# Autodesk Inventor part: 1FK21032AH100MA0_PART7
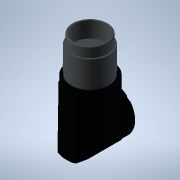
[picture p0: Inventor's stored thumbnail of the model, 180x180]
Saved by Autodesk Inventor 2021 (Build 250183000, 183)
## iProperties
Created: 2025-04
Part Number: 1FK21032AH100MA0_PART7
Material: Generic
Catalog Web Link: www.3dfindit.com
Description: -Servo synchronous motor
Document SubType Name: Modeling
Designer: psAdmin
Mass: 11.1504 g
Surface Area: 35.8996 cm^2
Volume: 11.1504 cm^3
Density: 1 g/cm^3
Appearance: PSOLRGB-176-176-176
Category: PARTsolutions
Title: 1FK21032AH100MA0_PART7
Author: Cadenas PARTsolutions
Comments: Servo synchronous motor
Sending System: PARTsolutions
Preprocessor: ST-DEVELOPER v19.3
PSOL_IDENT_0: {$CADENAS_DATA/23d-libs/siemens_ag/_cat_/12/33/1fk21032ah100ma0.prj},213 {VTYP=3D},{NB=1FK21032AH100
PSOL_IDENT_1: MA0_PART7},{LINA=1FK21032AH100MA0_PART7},{NN=1FK21032AH100MA0_PART7},{NOPRJ=TRUE},{DATE=19.08.2025 1
PSOL_IDENT_2: 4:00:27},{GEOMDATE=30.07.2025 02:02:58},{VERSION=},{LINEID=10},{WBVAR=},{WBNUMERIC=}  {NB=1FK21032AH
PSOL_IDENT_3: 100MA0_PART7},{LINA=1FK21032AH100MA0_PART7},{KT=DUMMY},{PREVIEW=../../../_pool_/d3/78/p_d211_xx_0093
PSOL_IDENT_4: 4j.png},{DESCSHORT=SIMOTICS S-1FK2 HD, SINAMICS S210 3AC 400V-480V, 0.59 Nm, 4500 rpm},{DESCLONG=SIM
PSOL_IDENT_5: OTICS S-1FK2 HD servo motor M0=0.64 Nm; PN = 0.28 kW at nN=4500 rpm (380-480 V); PN = 0.167 kW at nN=
PSOL_IDENT_6: 2500 rpm (200-240 V); with holding brake; degree of protection IP64; cylindrical shaft D14 x 30 mm;
PSOL_IDENT_7: absolute encoder 22-bit + 12-bit multiturn (encoder AM22DQC); with OCC interface; plug size M17, rot
PSOL_IDENT_8: atable; SIMOTICS S-1FK2 servomotorfor a wide range of uses in industrial environments. SIMOTICS S‑1F
PSOL_IDENT_9: K2 servomotors are compact synchronous motors with a high dynamic performance that set themselves ap
PSOL_IDENT_10: art as a result of their high power density, degree of protection and overload capability. The motor
PSOL_IDENT_11: s are available in two variants: as High Dynamic variant (highest dynamic performance as a result of
PSOL_IDENT_12: the low intrinsic moment of inertia for applications demanding a high dynamic performance with low
PSOL_IDENT_13: moved masses) - and as Compact variant (precise and stable closed-loop control for medium up to larg
PSOL_IDENT_14: e moved masses as a result of a medium intrinsic moment of inertia). SIMOTICSS‑1FK2 servomotors full
PSOL_IDENT_15: y exploit their strengths in a system with the SINAMICSS210 frequency converter and simple connectio
PSOL_IDENT_16: n using the one cable connection (OCC). Advantages include the short control and positioning times,
PSOL_IDENT_17: fast and precise correction of disturbing quantities as well as stable control with a high dynamic p
PSOL_IDENT_18: erformance. The servo motors can be configured to address a wide range of requirements. For example
PSOL_IDENT_19: with and without holding brake, IP64 or IP65 degree of protection, singleturn or multiturn absolute
PSOL_IDENT_20: encoders - to name just a few. Further, the servomotors are available in different shaft heights ext
PSOL_IDENT_21: ending from 20 to 100. A shaft sealing ring is available to achieve an IP65 degree of protection and
PSOL_IDENT_22: for subsequent mounting at the motor or as spare part. SIMOTICS - the optimum motor for each and ev
PSOL_IDENT_23: ery motion control application.},{INTNO=195125315563},{SUPPLIERALTNO=1FK2103-2AH10-0MA0},{MANUID=1FK
PSOL_IDENT_24: 21032AH100MA0},{MANUNAME=Siemens},{MANUTYPEDESC=SYNCHRONOUS MOTOR 1FK2 HD 0,64 NM},{AAU732=SIMOTICS}
PSOL_IDENT_25: ,{AAO057=S-1FK2},{AAU734=SIMOTICS S-1FK2 HD servo motor M0=0.64 Nm; PN = 0.28 kW at nN=4500 rpm (380
PSOL_IDENT_26: -480 V); PN = 0.167 kW at nN=2500 rpm (200-240 V); with holding brake; degree of protection IP64; cy
PSOL_IDENT_27: lindrical shaft D14 x 30 mm; absolute encoder 22-bit + 12-bit multiturn (encoder AM22DQC); with OCC
PSOL_IDENT_28: interface; plug size M17, rotatable;},{AAW338=SYNCHRONOUS MOTOR 1FK2 HD 0,64 NM},{AAO742=SIMOTICS},{
PSOL_IDENT_29: AAO663=4034106444723},{NOCUPEROU=1},{PRICEQUANTITY=1},{QUANTITYMIN=1},{QUANTITYINT=1},{CTN=85015100}
PSOL_IDENT_30: ,{COO=RO},{AAO676=1FK2103-2AH10-0MA0},{AAO677=Siemens AG},{ORDERUNIT=C62},{CONTENTUNIT=C62}
NB: 1FK21032AH100MA0_PART7
NT: Servo synchronous motor
NBSYN: $MANUID._PART7
LINA: 1FK21032AH100MA0_PART7
CATALOG: SIEMENS
PREVIEW: ../../../_pool_/d3/78/p_d211_xx_00934j.png
DESCSHORT: SIMOTICS S-1FK2 HD, SINAMICS S210 3AC 400V-480V, 0.59 Nm, 4500 rpm
DESCLONG: SIMOTICS S-1FK2 HD servo motor M0=0.64 Nm; PN = 0.28 kW at nN=4500 rpm (380-480 V); PN = 0.167 kW at nN=2500 rpm (200-240 V); with holding brake; degree of prot
INTNO: 195125315563
SUPPLIERALTNO: 1FK2103-2AH10-0MA0
MANUID: 1FK21032AH100MA0
MANUNAME: Siemens
MANUTYPEDESC: SYNCHRONOUS MOTOR 1FK2 HD 0,64 NM
AAU732: SIMOTICS
AAO057: S-1FK2
AAU734: SIMOTICS S-1FK2 HD servo motor M0=0.64 Nm; PN = 0.28 kW at nN=4500 rpm (380-480 V); PN = 0.167 kW at nN=2500 rpm (200-240 V); with holding brake; degree of prot
AAW338: SYNCHRONOUS MOTOR 1FK2 HD 0,64 NM
AAO742: SIMOTICS
AAO663: 4034106444723.0
NOCUPEROU: 1
PRICEQUANTITY: 1
QUANTITYMIN: 1
QUANTITYINT: 1
CTN: 85015100
COO: RO
ARTICLENO: 1FK21032AH100MA0_PART7
BOMINFO: 1FK21032AH100MA0_PART7
CREATOR: CADENAS GmbH
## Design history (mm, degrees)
feature "2025_04_17_15_06_16_0674"
body "Solid1"
